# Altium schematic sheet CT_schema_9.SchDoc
size 287 x 160 mm
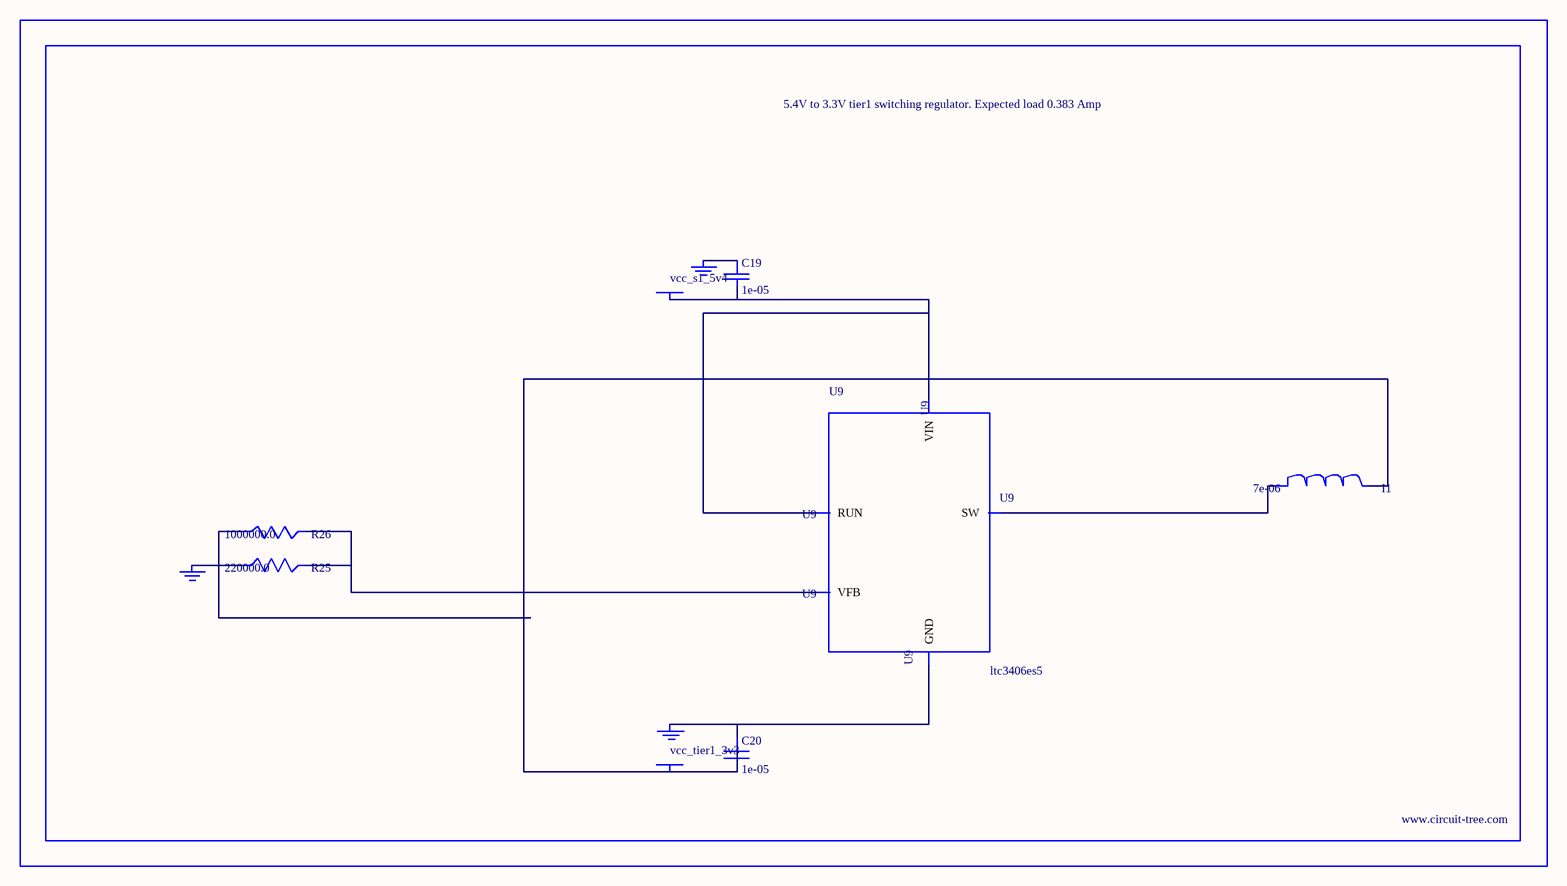
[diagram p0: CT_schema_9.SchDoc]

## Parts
BORDER8  (no value)
C19  1e-05  [C0805]
C20  1e-05  [C0805]
GND_INSTANCE_8_0  (no value)
GND_INSTANCE_8_1  (no value)
GND_INSTANCE_8_2  (no value)
I1  7e-06  [DR1040]
POWER_INSTANCE_8_0  vcc_tier1_3v3
POWER_INSTANCE_8_1  vcc_s1_5v4
R25  220000.0  [R0603]
R26  1000000.0  [R0603]
U9  ltc3406es5  [TSOT-23-5]

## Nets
NetC19_1: C19.1 GND_INSTANCE_8_1.0(GND)
NetC19_2: C19.2 POWER_INSTANCE_8_1.0(PWR) U9.1(RUN) U9.4(VIN)
NetC20_1: C20.1 GND_INSTANCE_8_0.0(GND) U9.2(GND)
NetC20_2: C20.2 I1.2 POWER_INSTANCE_8_0.0(PWR) R26.1
NetGND_INSTANCE_8_2_0: GND_INSTANCE_8_2.0(GND) R25.1
NetI1_1: I1.1 U9.3(SW)
NetR25_2: R25.2 R26.2 U9.5(VFB)

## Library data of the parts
BORDER8 = BORDER_PAGE8
C19 C20 = C0805C106K8RACTU
GND_INSTANCE_8_0-GND_INSTANCE_8_2 = GND
I1 = DR1040-7R0-R
POWER_INSTANCE_8_0 POWER_INSTANCE_8_1 = PWR
R25 = RC0603JR-07220KL
R26 = RC0603JR-071ML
